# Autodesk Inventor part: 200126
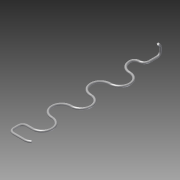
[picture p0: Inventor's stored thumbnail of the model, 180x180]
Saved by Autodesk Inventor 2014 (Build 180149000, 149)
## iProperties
Created: 2007-11
Part Number: 200126
Document SubType Name: Modeling
Designer: TH
Density: 8.08 g/cm^3
Mass: 46.0488 g
Surface Area: 57.2425 cm^2
Volume: 5.69911 cm^3
Material: Stainless Steel
Description: SPRING WIRE
Appearance: Steel
Component Category: Lower Component
Author: TH
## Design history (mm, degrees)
sketch "Sketch1"
  geometry: L1 (10, 0)-(-10, 0); L2 (-18, 8)-(-18, 17); L3 (-10, 25)-(0, 25); L4 (18.604, 2.713)-(19.729, 3.501); L5 (0, 223)-(-9, 223); L6 (0, 241)-(0, 246.786); L7 (0, 97)-(0, 133); L8 (0, 169)-(0, 205); A1 r 8 centre (-10, 17) between (-10, 25) and (-18, 17); A2 r 8 centre (-10, 8) between (-18, 8) and (-10, 0); A3 r 15 centre (10, 15) between (10, 0) and (18.604, 2.713); A4 r 18 centre (0, 43) between (0, 25) and (0, 61); A5 r 18 centre (0, 79) between (0, 97) and (0, 61); A6 r 18 centre (0, 151) between (0, 169) and (0, 133); A7 r 18 centre (0, 223) between (-18, 223) and (0, 205); A8 r 9 centre (-9, 223) between (-9, 232) and (-18, 223); A9 r 18 centre (0, 115) between (0, 97) and (0, 133); A10 r 18 centre (0, 187) between (0, 169) and (0, 205); A11 r 9 centre (-9, 241) between (-9, 232) and (0, 241); 6 further points
  constraints: 22 point on circle, 16 end point, 11 centre point, 9 tangent, 6 point on line, 3 midpoint, 2 collinear, 2 horizontal, 2 parallel, 1 coincident, 1 equal radius, 1 perpendicular, 14 other
  dimensions: "d1" = 5 horizontal distance of L4.end point (14.729, 0); "d2" = 35 deg angle of L1 L4; "d3" = 25 distance of point (-18, 0) point (-18, 25); "d5" = 8 radius of A1; "d6" = 18 distance from line of point (0, 0) L2; "d7" = 15 radius of A3; "d10" = 36 diameter of A4; "d11" = 36 diameter of A5 (= d10); "d13" = 36 diameter of A6 (= d10); "d17" = 18 radius of A7; "d18" = 9 radius of A8; "d19" = 151 distance from line of A6.centre L1; "d20" = 223 distance of L5.start point (0, 0); "d21" = 9 dimension on A11.centre; "d22" = 18 vertical distance of L5.start A11.centre; "d23" = 9 radius of A11
workplane "Work Plane1"
  workaxis "Work Axis1"
sketch "Sketch2"
  geometry: C1 r 2 at (0, 0); 1 further point
  constraints: 1 centre point
  dimensions: "d8" = 4 diameter of C1
sweep "Sweep2" sketch "Sketch2" dims "d24" = 0
sketch "Sketch3"
  geometry: L1 (246.786, 2)-(246.786, -2) reference; L2 (246.786, 0)-(255.786, 0); L3 (261.786, 6)-(261.786, 12.816); L4 (260.382, 16.673)-(257.59, 20); A1 r 6 centre (255.786, 6) between (255.786, 0) and (261.786, 6); A2 r 6 centre (255.786, 12.816) between (261.786, 12.816) and (260.382, 16.673); 3 further points
  constraints: 6 end point, 4 point on circle, 4 point on line, 4 tangent, 2 centre point, 2 perpendicular, 1 equal radius, 1 midpoint
  dimensions: "d25" = 15 distance of L2.start point (261.786, 0); "d26" = 15 distance of point (261.786, 0) point (261.786, 15); "d27" = 40 deg angle of L3 L4; "d28" = 5 vertical distance of point (261.786, 15) L4.end; "d29" = 6 radius of A1
sketch "Sketch4"
  geometry: C1 r 2 at (0, 0) reference
sweep "Sweep3" sketch "Sketch3", "Sketch4" dims "d30" = 0
body "Solid1"
other parameters: "d15" = 36 (= d10)
